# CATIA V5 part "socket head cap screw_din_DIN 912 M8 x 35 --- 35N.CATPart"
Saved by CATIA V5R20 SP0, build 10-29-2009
Part number: socket head cap screw_din_DIN 912 M8 x 35 --- 35N
Revision: ANY
Definition: UNKNOWN
Nomenclature: socket head cap screw_din_DIN 912 M8 x 35 --- 35N
Source: Unknown
Bounding box of the stored display mesh (mm): x 0 to 43, y -6.337 to 6.337, z -6.5 to 6.5
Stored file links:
  C:\Users\Utente\Desktop\IO LAVORO\3D X SITO CF\CUMSA\3D files CG\CG 864857\socket head cap screw_din_DIN 912 M8 x 35 --- 35N.CATPart
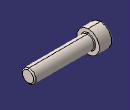
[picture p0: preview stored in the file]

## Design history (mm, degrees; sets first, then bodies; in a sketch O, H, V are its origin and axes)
Body1 "Hex" (main body)
  Solid1: solid without history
